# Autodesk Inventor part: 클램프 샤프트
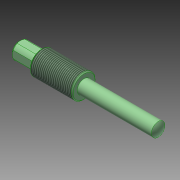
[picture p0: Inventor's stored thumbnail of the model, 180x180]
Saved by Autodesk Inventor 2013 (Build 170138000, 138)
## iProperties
Created: 2023-11
Part Number: 클램프 샤프트
Material: 강철, 탄소
Document SubType Name: Modeling
Designer: mdu-01
Density: 1 g/cm^3
Author: mdu-01
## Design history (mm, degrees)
sketch "스케치1"
  geometry: L1 (0, 0)-(84, 0); L2 (0, 0)-(0, 4); L3 (1, 5)-(13, 5); L4 (13, 5)-(13, 7); L5 (13, 7)-(38, 7); L6 (38, 7)-(38, 4); L7 (38, 4)-(82.472, 4); L8 (0, 4)-(1, 5); A1 r 6 centre (78, 0) between (84, 0) and (82.472, 4); 1 further point
  constraints: 16 end point, 4 parallel, 3 point on line, 2 perpendicular, 2 point on circle, 1 centre point, 1 horizontal
  dimensions: "d0" = 6 radius of A1; "d2" = 8 diameter of L7 L1; "d3" = 14 diameter of L5 L1; "d4" = 10 diameter of L3 L1; "d5" = 13 distance between parallel lines of L4 L2; "d6" = 46 distance from line of L1.end L6; "d7" = 25 distance between parallel lines of L6 L4; "d8" = 1 distance of L2.end point (0, 5); "d9" = 1 distance of L3.start point (0, 5) (= d8)
revolve "회전1" sketch "스케치1" stored, may be unused: angle "d10" = 90 deg
feature "스레드1" dims "d11" = 10, "d12" = 0
chamfer "모따기1" distance "d13" = 0.541; stored, may be unused: second distance "d14" = 2, angle "d15" = 45 deg
sketch "스케치2"
  geometry: L1 (2.179, -4.5)-(-2.179, -4.5); L2 (-4.5, -2.179)-(-4.5, 2.179); L3 (-2.179, 4.5)-(2.179, 4.5); L4 (4.5, 2.179)-(4.5, -2.179); L5 (4.5, -4.5)-(-4.5, 4.5); L6 (-4.5, -4.5)-(4.5, 4.5); 2 further points
  constraints: 12 end point, 4 point on line, 2 horizontal alignment, 2 midpoint, 2 parallel, 2 vertical alignment, 1 horizontal, 1 perpendicular, 9 other
  dimensions: "d16" = 9 distance of L5.end L6.end; "d17" = 9 distance of L6.start L5.end
extrude "돌출1" cut sketch "스케치2" distance "d18" = 12; taper "d19" = 0 deg
sketch "스케치3"
  geometry: L1 (0, 0)-(-4.949, 0); L2 (-4.949, 0)-(-4.371, 1); L3 (-4.371, 1)-(-1.949, 1); L4 (-1.949, 1)-(0, 2.125); L5 (0, 2.125)-(0, 0)
  constraints: 10 end point, 1 horizontal, 1 parallel, 1 perpendicular
  dimensions: "d20" = 60 deg angle of L1 L2; "d21" = 2 diameter of L3 L1; "d23" = 3 horizontal distance of L3.end L1.end; "d24" = 30 deg angle of L1 L4; "d25" = 4.25 diameter of L4.end L1
revolve "회전2" sketch "스케치3" stored, may be unused: angle "d26" = 90 deg
node "솔리드1"
